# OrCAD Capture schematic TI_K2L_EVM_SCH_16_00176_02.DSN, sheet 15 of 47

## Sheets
15 PAGE38 : K2L_XDS200_2: size C; title: XDS200 / AM1802,  boot mode, reset, XDS200 power
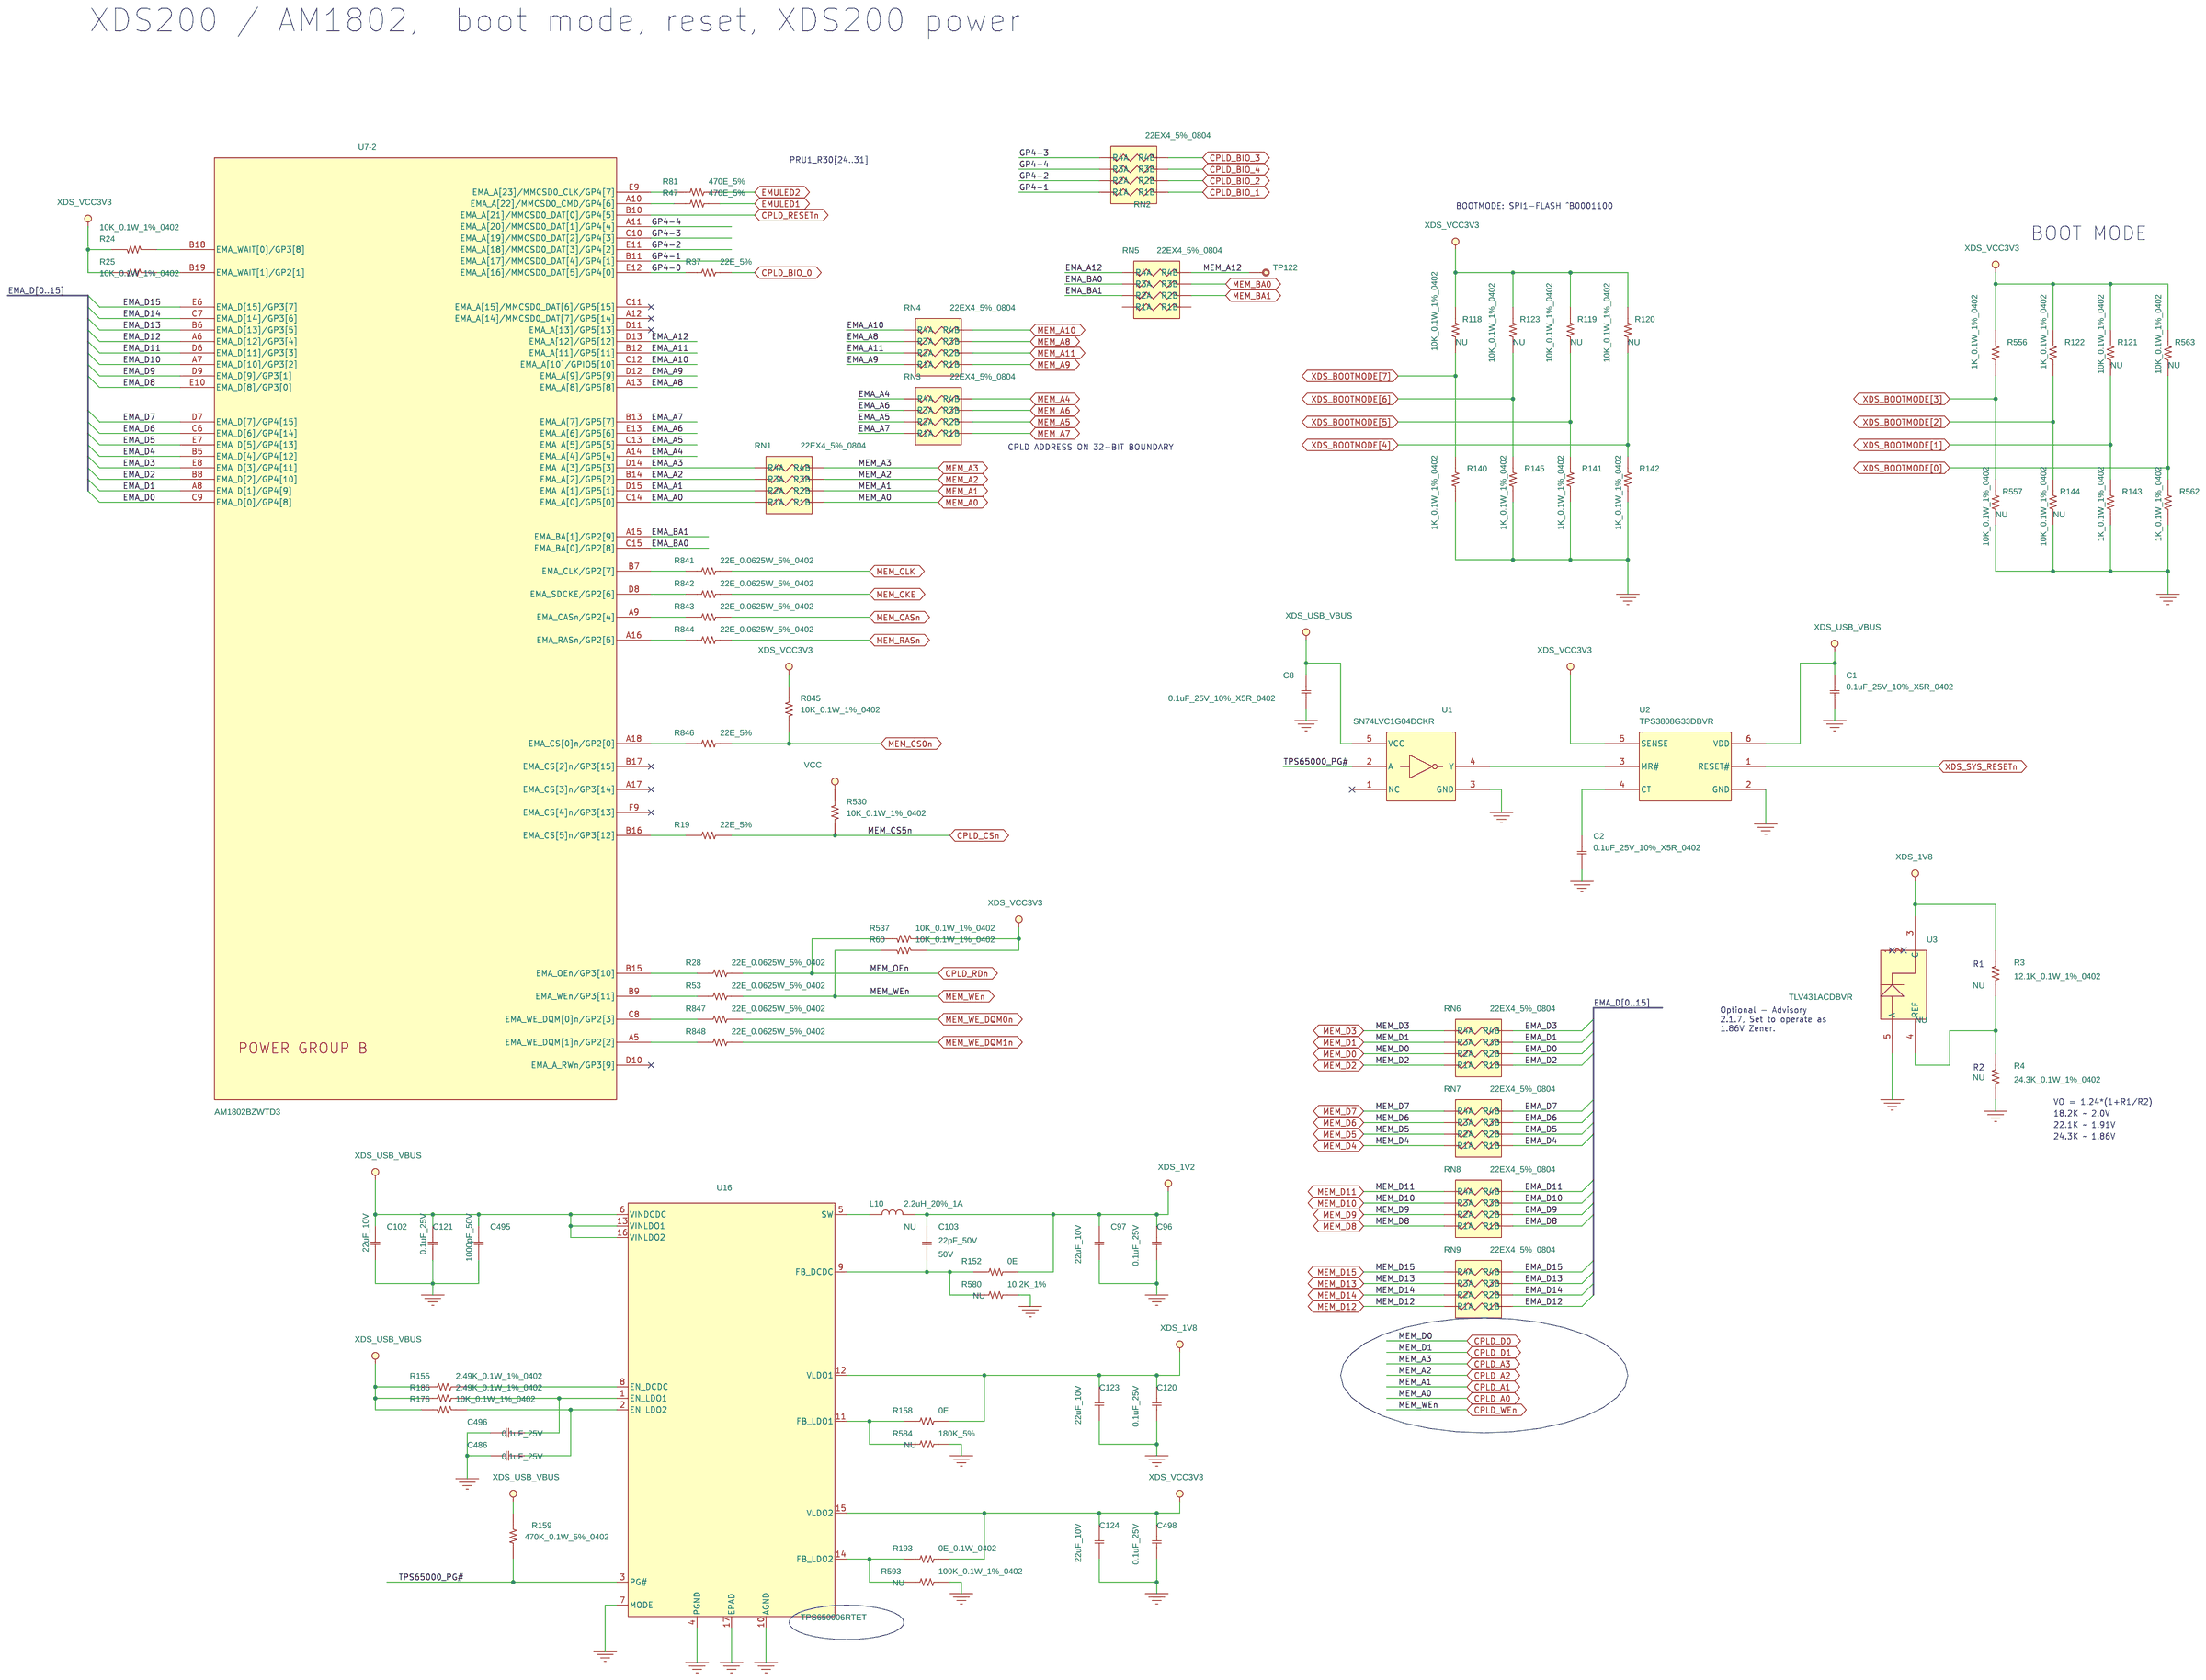
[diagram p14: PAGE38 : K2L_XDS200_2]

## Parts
sheet PAGE38 : K2L_XDS200_2
C1  0.1uF_25V_10%_X5R_0402  [C0402]
C2  0.1uF_25V_10%_X5R_0402  [C0402]
C8  0.1uF_25V_10%_X5R_0402  [C0402]
C96  0.1uF_25V  [C0402]
C97  22uF_10V  [C0805]
C102  22uF_10V  [C0805]
C103  22pF_50V  [C0402]
C120  0.1uF_25V  [C0402]
C121  0.1uF_25V  [C0402]
C123  22uF_10V  [C0805]
C124  22uF_10V  [C0805]
C486  0.1uF_25V  [C0402]
C495  1000pF_50V  [C0402]
C496  0.1uF_25V  [C0402]
C498  0.1uF_25V  [C0402]
L10  2.2uH_20%_1A  [IND1008]
R3  12.1K_0.1W_1%_0402  [R0402]
R4  24.3K_0.1W_1%_0402  [R0402]
R19  22E_5%  [R0402]
R24  10K_0.1W_1%_0402  [R0402]
R25  10K_0.1W_1%_0402  [R0402]
R28  22E_0.0625W_5%_0402  [R0402]
R37  22E_5%  [R0402]
R47  470E_5%  [R0402]
R53  22E_0.0625W_5%_0402  [R0402]
R60  10K_0.1W_1%_0402  [R0402]
R81  470E_5%  [R0402]
R118  10K_0.1W_1%_0402  [R0402]
R119  10K_0.1W_1%_0402  [R0402]
R120  10K_0.1W_1%_0402  [R0402]
R121  10K_0.1W_1%_0402  [R0402]
R122  1K_0.1W_1%_0402  [R0402]
R123  10K_0.1W_1%_0402  [R0402]
R140  1K_0.1W_1%_0402  [R0402]
R141  1K_0.1W_1%_0402  [R0402]
R142  1K_0.1W_1%_0402  [R0402]
R143  1K_0.1W_1%_0402  [R0402]
R144  10K_0.1W_1%_0402  [R0402]
R145  1K_0.1W_1%_0402  [R0402]
R152  0E  [R0402]
R155  2.49K_0.1W_1%_0402  [R0402]
R158  0E  [R0402]
R159  470K_0.1W_5%_0402  [R0402]
R176  10K_0.1W_1%_0402  [R0402]
R186  2.49K_0.1W_1%_0402  [R0402]
R193  0E_0.1W_0402  [R0402]
R530  10K_0.1W_1%_0402  [R0402]
R537  10K_0.1W_1%_0402  [R0402]
R556  1K_0.1W_1%_0402  [R0402]
R557  10K_0.1W_1%_0402  [R0402]
R562  1K_0.1W_1%_0402  [R0402]
R563  10K_0.1W_1%_0402  [R0402]
R580  10.2K_1%  [R0402]
R584  180K_5%  [R0402]
R593  100K_0.1W_1%_0402  [R0402]
R841  22E_0.0625W_5%_0402  [R0402]
R842  22E_0.0625W_5%_0402  [R0402]
R843  22E_0.0625W_5%_0402  [R0402]
R844  22E_0.0625W_5%_0402  [R0402]
R845  10K_0.1W_1%_0402  [R0402]
R846  22E_5%  [R0402]
R847  22E_0.0625W_5%_0402  [R0402]
R848  22E_0.0625W_5%_0402  [R0402]
RN1  22EX4_5%_0804  [RESN_EXBN8V_0402X4]
RN2  22EX4_5%_0804  [RESN_EXBN8V_0402X4]
RN3  22EX4_5%_0804  [RESN_EXBN8V_0402X4]
RN4  22EX4_5%_0804  [RESN_EXBN8V_0402X4]
RN5  22EX4_5%_0804  [RESN_EXBN8V_0402X4]
RN6  22EX4_5%_0804  [RESN_EXBN8V_0402X4]
RN7  22EX4_5%_0804  [RESN_EXBN8V_0402X4]
RN8  22EX4_5%_0804  [RESN_EXBN8V_0402X4]
RN9  22EX4_5%_0804  [RESN_EXBN8V_0402X4]
TP122  TP  [TP-S40]
U1  SN74LVC1G04DCKR  [SC70_5p]
U2  TPS3808G33DBVR  [SOT23_6]
U3  TLV431ACDBVR  [dbv-20x60-5]
U16  TPS650006RTET  [QFN50P300X300X80-17N_A_EINF]
sheet PAGE39 : K2L_XDS200_3
U7  AM1802BZWTD3  [BGA80P_16X16_361]  (sections -1,-10,-11,-12,-13,-14,-15,-16,-2,-3,-4,-5,-6,-7,-8,-9)

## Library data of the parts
C1 C2 C8 = 11_C_12: CAP CER 0.1UF 25V 10% X5R 0402; Alt Mfg: Taiyo Yuden; Distributor_name: DIGIKEY; Distributor_part_number: 445-4964-1-ND; EIC Part#: 03_00470_02; Manufacture: TDK Corporation; Manufacture Part Number: C1005X5R1E104K050BC; Manufacture(English): TDK Corporation; Manufacture_Part_Number: GRM155R61E104KA87D; Manufacturer: TDK Corporation; Manufacturer_Part_No: C1005X5R1E104K050BC; Mfg: Murata Electronics North America; Mfg Part#: 03_00470_02; Mfr_name: TDK Corporation; Mfr_part_number: C1005X5R1E104K050BC; Oper. Temp. Range: -55°C ~ 85°C; Package: 0402; Price @ 1: 0.10000; Price @ 1K: 0.00960; ProcessType: SMT; RoHS: Yes; Tolerance: 10%; Vendor: DIGIKEY; Vendor Part#: 445-4964-1-ND; Vendor_Part_No: 445-4964-1-ND; eI Part#: 03_00470_02
C96 C120 C121 C486 C496 C498 = 11_C_0: CAP CER 0.1UF 25V 10% X5R 0402; Alt Mfg: Taiyo Yuden; Distributor_name: DIGIKEY; Distributor_part_number: 445-4964-1-ND; EIC Part#: 03_00470_02; Manufacture: TDK Corporation; Manufacture Part Number: C1005X5R1E104K050BC; Manufacture(English): TDK Corporation; Manufacture_Part_Number: GRM155R61E104KA87D; Manufacturer: TDK Corporation; Manufacturer_Part_No: C1005X5R1E104K050BC; Mfg: Murata Electronics North America; Mfg Part#: 03_00470_02; Mfr_name: TDK Corporation; Mfr_part_number: C1005X5R1E104K050BC; Oper. Temp. Range: -55°C ~ 85°C; Package: 0402; Price @ 1: 0.10000; Price @ 1K: 0.00960; ProcessType: SMT; RoHS: Yes; Tolerance: 10%; Vendor: DIGIKEY; Vendor Part#: 445-4964-1-ND; Vendor_Part_No: 445-4964-1-ND; eI Part#: 03_00470_02
C97 C102 C123 C124 = 11_C_12: CAP CER 22UF 10V 20% X5R 0805; Characteristic: <Characteristic>; Distributor_name: DIGIKEY; Distributor_part_number: 587-1958-1-ND; EIC Part#: 03_00263_01; Manufacture: Taiyo Yuden; Manufacture Part Number: LMK212BJ226MG-T; Manufacture(English): Taiyo Yuden; Manufacture_Part_Number: LMK212BJ226MG-T; Manufacturer: Taiyo Yuden; Manufacturer_Part_No: LMK212BJ226MG-T; Mfg: Taiyo Yuden; Mfg Part#: 03_00263_01; Mfr_name: Taiyo Yuden; Mfr_part_number: LMK212BJ226MG-T; Oper. Temp. Range: -55C to 85C; Package: 0805; Price @ 1: 0.53000; Price @ 10K: 0.12000; Price @ 1K: 0.16875; ProcessType: SMT; RoHS: Yes; Tolerance: 20%; Vendor: DIGIKEY; Vendor Part#: 587-1958-1-ND; Vendor_Part_No: 587-1958-1-ND; Voltage: 10V; eI Part#: 03_00263_01
C103 = 11_C_0: CAP CER 22PF 50V 0402 SMD; Alt Mfg: Yageo; Alt Mfg Part#: CC0402JRNPO9BN220; Alternate_Mfr: TDK Corporation; Alternate_Partno: C1005C0G1H220J050BA; Distributor_name: DIGIKEY; Distributor_part_number: PCC220CQCT-ND; EIC Part#: 03_00204_02; Manufacture: Panasonic - ECG; Manufacture Part Number: ECJ-0EC1H220J; Manufacture(English): Panasonic - ECG; Manufacture_Part_Number: ECJ-0EC1H220J; Manufacturer: Panasonic - ECG; Manufacturer_Part_No: ECJ-0EC1H220J; Mfg: Panasonic - ECG; Mfg Part#: 03_00204_02; Mfr_name: Panasonic - ECG; Mfr_part_number: ECJ-0EC1H220J; Mounting Status: NU; Mounting_Status: NU; Oper. Temp. Range: -55C to 125C; Package: 0402; Price @ 1: TBD; Price @ 10K: TBD; Price @ 1K: TBD; ProcessType: SMT; RoHS: Yes; Tolerance: 5%; Vendor: DIGIKEY; Vendor Part#: PCC220CQCT-ND; Vendor_Part_No: PCC220CQCT-ND; Voltage: 50V; eI Part#: 03_00204_02
C495 = 11_C_0: CAP CER 1000PF 50V 10% X7R 0402; Advansus_Part_Number: 11G232110214030; Distributor_name: DIGIKEY; Distributor_part_number: 1276-1493-1-ND; EIC Part#: 03_00591_01; Manufacture: Samsung; Manufacture Part Number: CL05B102KB5NFNC; Manufacture(English): Samsung; Manufacture_Part_Number: CL05B102KB5NFNC; Manufacturer: Samsung; Manufacturer_Part_No: CL05B102KB5NFNC; Mfg: Samsung; Mfg Part#: CL05B102KB5NFNC; Mfr_name: Samsung; Mfr_part_number: CL05B102KB5NFNC; Oper. Temp. Range: -55C to 85C; Package: 0402; Price @ 1: 0.10000; Price @ 10K: 0.00260; Price @ 1K: 0.00372; ProcessType: SMT; RoHS: Yes; Tolerance: 10%; Vendor: DIGIKEY; Vendor Part#: 1276-1493-1-ND; Vendor_Part_No: 1276-1493-1-ND; Voltage: 50V; eI Part#: 03_00591_01
L10 = 1211_CHOKE_0: INDUCTOR 2.2UH; Current: 2.3A Irms; Distributor_name: DIGIKEY; Distributor_part_number: 490-6700-1-ND; EIC Part#: 04_00407_01; Manufacture: Murata; Manufacture Part Number: LQM2HPN2R2MJ0L; Manufacture(English): Murata; Manufacture_Part_Number: LQM2HPN2R2MJ0L; Manufacturer: Murata; Manufacturer_Part_No: LQM2HPN2R2MJ0L; Mfg Part#: 04_00407_01; Mfr_name: Murata; Mfr_part_number: LQM2HPN2R2MJ0L; ProcessType: SMT; RoHS: Yes; Tolerance: 20%; Vendor: DIGIKEY; Vendor Part#: LQM2HPN2R2MJ0L; Vendor_Part_No: 490-6700-1-ND; eI Part#: 04_00407_01
R3 = 10_R_0: RES 12.1K OHM 1/10W 1% 0402 SMD; Alt Mfg: Yageo; Alt Mfg Part#: RC0402FR-0710KL; Distributor_name: DIGIKEY; Distributor_part_number: P12.1KLCT-ND; EIC Part#: 02_00497_01; Manufacture: Panasonic - ECG; Manufacture Part Number: ERJ-2RKF1212X; Manufacture(English): Panasonic - ECG; Manufacture_Part_Number: ERJ-2RKF1212X; Manufacturer: Panasonic - ECG; Manufacturer_Part_No: ERJ-2RKF1212X; Mfg Part#: 02_00497_01; Mfr_name: Panasonic - ECG; Mfr_part_number: ERJ-2RKF1212X; Mounting: NU; Mounting Status: NU; Mounting_Status: NU; Oper. Temp. Range: -55C to 125C; Package: 0402; ProcessType: SMT; Remark: Alt part is 1/16W; RoHS: Yes; Tolerance: 1%; Vendor: DIGIKEY; Vendor Part#: P12.1KLDKR-ND; Vendor_Part_No: P12.1KLCT-ND; eI Part#: 02_00027_01
R4 = 10_R_0: RES 24.3K OHM 1/10W 1% 0402 SMD; Alt Mfg: Yageo; Alt Mfg Part#: RC0402FR-0710KL; Distributor_name: DIGIKEY; Distributor_part_number: P24.3KLCT-ND; EIC Part#: 02_00786_01; Manufacture: Panasonic - ECG; Manufacture Part Number: ERJ-2RKF2432X; Manufacture(English): Panasonic - ECG; Manufacture_Part_Number: ERJ-2RKF2432X; Manufacturer: Panasonic - ECG; Manufacturer_Part_No: ERJ-2RKF2432X; Mfg Part#: 02_00786_01; Mfr_name: Panasonic - ECG; Mfr_part_number: ERJ-2RKF2432X; Mounting: NU; Mounting Status: NU; Mounting_Status: NU; Oper. Temp. Range: -55C to 125C; Package: 0402; ProcessType: SMT; Remark: Alt part is 1/16W; RoHS: Yes; Tolerance: 1%; Vendor: DIGIKEY; Vendor Part#: P24.3KLCT-ND; Vendor_Part_No: P24.3KLCT-ND; eI Part#: 02_00497_01
R19 R28 R37 R53 R841-R844 R846-R848 = 10_R_0: RES 22 OHM 1/16W 1% 0402 SMD; Characteristic: 5%; Distributor_name: DIGIKEY; Distributor_part_number: P22JCT-ND; EIC Part#: 02_00233_01; Manufacture: Panasonic - ECG; Manufacture Part Number: ERJ-2GEJ220X; Manufacture(English): Panasonic - ECG; Manufacture_Part_Number: ERJ-2GEJ220X; Manufacturer: Panasonic - ECG; Manufacturer_Part_No: ERJ-2GEJ220X; Mfg: Panasonic - ECG; Mfg Part#: ERJ-2GEJ220X; Mfr_name: Panasonic - ECG; Mfr_part_number: ERJ-2GEJ220X; Oper. Temp. Range: -55C to 125C; Package: 0402; ProcessType: SMT; RoHS: Yes; Tolerance: 5%; Vendor: DIGIKEY; Vendor Part#: P22JCT-ND; Vendor_Part_No: P22JCT-ND; eI Part#: 02_00233_01
R24 R25 R60 R530 R537 R845 = 10_R_0: RES 10K OHM 1/10W 1% 0402 SMD; Alt Mfg: Yageo; Alt Mfg Part#: RC0402FR-0710KL; Distributor_name: DIGIKEY; Distributor_part_number: P10.0KLCT-ND; EIC Part#: 02_00027_01; Manufacture: Panasonic - ECG; Manufacture Part Number: ERJ-2RKF1002X; Manufacture(English): Panasonic - ECG; Manufacture_Part_Number: ERJ-2RKF1002X; Manufacturer: Panasonic - ECG; Manufacturer_Part_No: ERJ-2RKF1002X; Mfg Part#: 02_00027_01; Mfr_name: Panasonic - ECG; Mfr_part_number: ERJ-2RKF1002X; Oper. Temp. Range: -55C ~ 125C; Package: 0402; Price @ 1: 0.10000; Price @ 10K: 0.00347; Price @ 1K: 0.00672; ProcessType: SMT; Remark: Alt part is 1/16W; RoHS: Yes; Tolerance: 1%; Vendor: DIGIKEY; Vendor Part#: P10.0KLCT-ND; Vendor_Part_No: P10.0KLCT-ND; eI Part#: 02_00027_01
R47 = 10_R_0: RES 470 OHM 1/10W 5% 0402 SMD; Alt Mfg: Yageo; Alt Mfg Part#: RC0402JR-070RL; Distributor_name: DIGIKEY; Distributor_part_number: P470JCT-ND; EIC Part#: 02_00483_01; Manufacture: Panasonic - ECG; Manufacture Part Number: ERJ-2GEJ471X; Manufacture(English): Panasonic - ECG; Manufacture_Part_Number: ERJ-2GEJ471X; Manufacturer: Panasonic - ECG; Manufacturer_Part_No: ERJ-2GEJ471X; Mfg Part#: 02_00483_01; Mfr_name: Panasonic - ECG; Mfr_part_number: ERJ-2GEJ471X; Oper. Temp. Range: -55C to 125C; Package: 0402; ProcessType: SMT; Remark: Alt part is 1/16W; RoHS: Yes; Tolerance: 5%; Vendor: DIGIKEY; Vendor Part#: P470JDKR-ND; Vendor_Part_No: P470JCT-ND; eI Part#: 02_00483_01
R81 = 10_R_0: RES 470 OHM 1/10W 5% 0402 SMD; Alt Mfg: Yageo; Alt Mfg Part#: RC0402JR-070RL; Distributor_name: DIGIKEY; Distributor_part_number: P470JCT-ND; EIC Part#: 02_00483_01; Manufacture: Panasonic - ECG; Manufacture Part Number: ERJ-2GEJ471X; Manufacture(English): Panasonic - ECG; Manufacture_Part_Number: ERJ-2GEJ471X; Manufacturer: Panasonic - ECG; Manufacturer_Part_No: ERJ-2GEJ471X; Mfg Part#: 02_00483_01; Mfr_name: Panasonic - ECG; Mfr_part_number: ERJ-2GEJ471X; Oper. Temp. Range: -55C to 125C; Package: 0402; ProcessType: SMT; Remark: Alt part is 1/16W; RoHS: Yes; Tolerance: 5%; Vendor: DIGIKEY; Vendor Part#: P470JDKR-ND; Vendor_Part_No: P470JCT-ND; eI Part#: 02_00027_01
R118-R120 R123 = 10_R_0: RES 10K OHM 1/10W 1% 0402 SMD; Alt Mfg: Yageo; Alt Mfg Part#: RC0402FR-0710KL; Distributor_name: DIGIKEY; Distributor_part_number: P10.0KLCT-ND; EIC Part#: 02_00027_01; Manufacture: Panasonic - ECG; Manufacture Part Number: ERJ-2RKF1002X; Manufacture(English): Panasonic - ECG; Manufacture_Part_Number: ERJ-2RKF1002X; Manufacturer: Panasonic - ECG; Manufacturer_Part_No: ERJ-2RKF1002X; Mfg Part#: 02_00027_01; Mfr_name: Panasonic - ECG; Mfr_part_number: ERJ-2RKF1002X; Mounting: NU; Mounting Status: NU; Mounting_Status: NU; Oper. Temp. Range: -55C ~ 125C; Package: 0402; Price @ 1: 0.10000; Price @ 10K: 0.00347; Price @ 1K: 0.00672; ProcessType: SMT; Remark: Alt part is 1/16W; RoHS: Yes; Tolerance: 1%; Vendor: DIGIKEY; Vendor Part#: P10.0KLCT-ND; Vendor_Part_No: P10.0KLCT-ND; eI Part#: 02_00027_01
R121 R144 R557 R563 = 10_R_0: RES 10K OHM 1/10W 1% 0402 SMD; Alt Mfg: Yageo; Alt Mfg Part#: RC0402FR-0710KL; Distributor_name: DIGIKEY; Distributor_part_number: P10.0KLCT-ND; EIC Part#: 02_00027_01; Manufacture: Panasonic - ECG; Manufacture Part Number: ERJ-2RKF1002X; Manufacture(English): Panasonic - ECG; Manufacture_Part_Number: ERJ-2RKF1002X; Manufacturer: Panasonic - ECG; Manufacturer_Part_No: ERJ-2RKF1002X; Mfg Part#: 02_00027_01; Mfr_name: Panasonic - ECG; Mfr_part_number: ERJ-2RKF1002X; Mounting: NU; Mounting Status: NU; Mounting_Status: NU; Oper. Temp. Range: -55C ~ 125C; Package: 0402; Price @ 1: 0.10000; Price @ 10K: 0.00347; Price @ 1K: 0.00672; ProcessType: SMT; Remark: Alt part is 1/16W; RoHS: Yes; Vendor: DIGIKEY; Vendor Part#: P10.0KLCT-ND; Vendor_Part_No: P10.0KLCT-ND; eI Part#: 02_00027_01
R122 R143 R556 R562 = 10_R_0: RES 1.00K OHM 1/10W 1% 0402 SMD; Alt Mfg: Yageo; Distributor_name: DIGIKEY; Distributor_part_number: P1.00KLCT-ND; EIC Part#: 02_00045_01; MOUNTED: <MOUNTED>; Manufacture: Panasonic - ECG; Manufacture Part Number: ERJ-2RKF1001X; Manufacture(English): Panasonic - ECG; Manufacture_Part_Number: ERJ-2RKF1001X; Manufacturer: Panasonic - ECG; Manufacturer_Part_No: ERJ-2RKF1001X; Mfg Part#: 02_00045_01; Mfr_name: Panasonic - ECG; Mfr_part_number: ERJ-2RKF1001X; Oper. Temp. Range: -55C to 125C; Package: 0402; ProcessType: SMT; RoHS: Yes; Vendor: DIGIKEY; Vendor Part#: P1.00KLCT-ND; Vendor_Part_No: P1.00KLCT-ND; eI Part#: 02_00045_01
R140-R142 R145 = 10_R_0: RES 1.00K OHM 1/10W 1% 0402 SMD; Alt Mfg: Yageo; Distributor_name: DIGIKEY; Distributor_part_number: P1.00KLCT-ND; EIC Part#: 02_00045_01; MOUNTED: <MOUNTED>; Manufacture: Panasonic - ECG; Manufacture Part Number: ERJ-2RKF1001X; Manufacture(English): Panasonic - ECG; Manufacture_Part_Number: ERJ-2RKF1001X; Manufacturer: Panasonic - ECG; Manufacturer_Part_No: ERJ-2RKF1001X; Mfg Part#: 02_00045_01; Mfr_name: Panasonic - ECG; Mfr_part_number: ERJ-2RKF1001X; Oper. Temp. Range: -55C to 125C; Package: 0402; ProcessType: SMT; RoHS: Yes; Tolerance: 1%; Vendor: DIGIKEY; Vendor Part#: P1.00KLCT-ND; Vendor_Part_No: P1.00KLCT-ND; eI Part#: 02_00045_01
R152 R158 R193 = 10_R_0: RES 0.0 OHM 1/10W JUMP 0402 SMD; Alt Mfg: Yageo; Distributor_name: DIGIKEY; Distributor_part_number: P0.0JCT-ND; EIC Part#: 02_00019_01; Manufacture: Panasonic - ECG; Manufacture Part Number: ERJ-2GE0R00X; Manufacture(English): Panasonic - ECG; Manufacture_Part_Number: ERJ-2GE0R00X; Manufacturer: Panasonic - ECG; Manufacturer_Part_No: ERJ-2GE0R00X; Mfg Part#: 02_00019_01; Mfr_name: Panasonic - ECG; Mfr_part_number: ERJ-2GE0R00X; Oper. Temp. Range: -55C to 125C; Package: 0402; ProcessType: SMT; Remark: Alt part is 1/16W; RoHS: Yes; Tolerance: 5%; Vendor: DIGIKEY; Vendor Part#: P0.0JCT-ND; Vendor_Part_No: P0.0JCT-ND; eI Part#: 02_00019_01
R155 R186 = 10_R_0: RES 2.49K OHM 1/10W 1% 0402 SMD; Alt Mfg: Yageo; Alt Mfg Part#: RC0402FR-071KL; Distributor_name: DIGIKEY; Distributor_part_number: P2.49KLCT-ND; EIC Part#: 02_00794_01; MOUNTED: <MOUNTED>; Manufacture: Panasonic - ECG; Manufacture Part Number: ERJ-2RKF2491X; Manufacture(English): Panasonic - ECG; Manufacture_Part_Number: ERJ-2RKF2491X; Manufacturer: Panasonic - ECG; Manufacturer_Part_No: ERJ-2RKF2491X; Mfg Part#: 02_00794_01; Mfr_name: Panasonic - ECG; Mfr_part_number: ERJ-2RKF2491X; Oper. Temp. Range: -55C to 125C; Package: 0402; ProcessType: SMT; RoHS: Yes; Vendor: DIGIKEY; Vendor Part#: P2.49KLTR-ND; Vendor_Part_No: P2.49KLCT-ND; eI Part#: NA
R159 = 10_R_0: RES 470K OHM 1/10W 5% 0402 SMD; Alt Mfg: Yageo; Alt Mfg Part#: RC0402FR-0710KL; Distributor_name: DIGIKEY; Distributor_part_number: P470KJCT-ND; EIC Part#: 02_00200_04; Manufacture: Panasonic - ECG; Manufacture Part Number: ERJ-2GEJ474X; Manufacture(English): Panasonic - ECG; Manufacture_Part_Number: ERJ-2GEJ474X; Manufacturer: Panasonic - ECG; Manufacturer_Part_No: ERJ-2GEJ474X; Mfg Part#: 02_00200_04; Mfr_name: Panasonic - ECG; Mfr_part_number: ERJ-2GEJ474X; Oper. Temp. Range: -55C ~ 125C; Package: 0402; ProcessType: SMT; Remark: Alt part is 1/10W; RoHS: Yes; Tolerance: 1%; Vendor: DIGIKEY; Vendor Part#: P470KJCT-ND; Vendor_Part_No: P470KJCT-ND; eI Part#: NA
R176 = 10_R_0: RES 10K OHM 1/10W 1% 0402 SMD; Alt Mfg: Yageo; Alt Mfg Part#: RC0402FR-0710KL; Distributor_name: DIGIKEY; Distributor_part_number: P10.0KLCT-ND; EIC Part#: 02_00027_01; Manufacture: Panasonic - ECG; Manufacture Part Number: ERJ-2RKF1002X; Manufacture(English): Panasonic - ECG; Manufacture_Part_Number: ERJ-2RKF1002X; Manufacturer: Panasonic - ECG; Manufacturer_Part_No: ERJ-2RKF1002X; Mfg Part#: 02_00027_01; Mfr_name: Panasonic - ECG; Mfr_part_number: ERJ-2RKF1002X; Oper. Temp. Range: -55C ~ 125C; Package: 0402; Price @ 1: 0.10000; Price @ 10K: 0.00347; Price @ 1K: 0.00672; ProcessType: SMT; Remark: Alt part is 1/16W; RoHS: Yes; Vendor: DIGIKEY; Vendor Part#: P10.0KLCT-ND; Vendor_Part_No: P10.0KLCT-ND; eI Part#: 02_00027_01
R580 = 10_R_0: RES 10.2K OHM 1/10W 1% 0402 SMD; Alt Mfg: Yageo; Alt Mfg Part#: RC0402FR-0710KL; Distributor_name: ELEMENT14; Distributor_part_number: 2282634; EIC Part#: 02_00720_01; Manufacture: Panasonic - ECG; Manufacture Part Number: ERJ-2RKF1022X; Manufacture(English): Panasonic - ECG; Manufacture_Part_Number: ERJ-2RKF1022X; Manufacturer: Panasonic - ECG; Manufacturer_Part_No: ERJ-2RKF1022X; Mfg Part#: 02_00720_01; Mfr_name: Panasonic - ECG; Mfr_part_number: ERJ-2RKF1022X; Mounting Status: NU; Mounting_Status: NU; Oper. Temp. Range: -55C ~ 125C; Package: 0402; ProcessType: SMT; Remark: Alt part is 1/10W; RoHS: Yes; Tolerance: 1%; Vendor: ELEMENT14; Vendor Part#: P10.2KLCT-ND; Vendor_Part_No: 2282634; eI Part#: 02_00027_01
R584 = 10_R_0: RES 180K OHM 1/10W 5% 0402 SMD; Alt Mfg: Yageo; Alt Mfg Part#: RC0402FR-0710KL; Distributor_name: DIGIKEY; Distributor_part_number: P180KJCT-ND; EIC Part#: TBD; Manufacture: Panasonic - ECG; Manufacture Part Number: ERJ-2GEJ184X; Manufacture(English): Panasonic - ECG; Manufacture_Part_Number: ERJ-2GEJ184X; Manufacturer: Panasonic - ECG; Manufacturer_Part_No: ERJ-2GEJ184X; Mfg Part#: TBD; Mfr_name: Panasonic - ECG; Mfr_part_number: ERJ-2GEJ184X; Mounting Status: NU; Mounting_Status: NU; Oper. Temp. Range: -55C ~ 125C; Package: 0402; ProcessType: SMT; Remark: Alt part is 1/10W; RoHS: Yes; Tolerance: 1%; Vendor: DIGIKEY; Vendor Part#: P180KJCT-ND; Vendor_Part_No: P180KJCT-ND; eI Part#: NA
R593 = 10_R_0: RES 100K OHM 1/10W 1% 0402 SMD; Alt Mfg: Yageo; Alt Mfg Part#: RC0402FR-07100KL; Distributor_name: DIGIKEY; Distributor_part_number: P100KLCT-ND; EIC Part#: 02_00262_01; Manufacture: Panasonic - ECG; Manufacture Part Number: ERJ-2RKF1003X; Manufacture(English): Panasonic - ECG; Manufacture_Part_Number: ERJ-2RKF1003X; Manufacturer: Panasonic - ECG; Manufacturer_Part_No: ERJ-2RKF1003X; Mfg Part#: 02_00262_01; Mfr_name: Panasonic - ECG; Mfr_part_number: ERJ-2RKF1003X; Mounting Status: NU; Mounting_Status: NU; Oper. Temp. Range: ±100ppm/°C; Package: 0402; ProcessType: SMT; RoHS: Yes; Tolerance: 1%; Vendor: DIGIKEY; Vendor Part#: P100KLCT-ND; Vendor_Part_No: P100KLCT-ND; eI Part#: 02_00019_01
RN1-RN9 = R-Pak4: RES ARRAY 22 OHM 4 RES 0804; Distributor_name: DigiKey; Distributor_part_number: Y10220CT-ND; EIC Part#: 02_00972_01; Manufacture: Panasonic - ECG; Manufacture Part Number: EXB-N8V220JX; Manufacture(English): Panasonic - ECG; Manufacture_Part_Number: EXB-N8V220JX; Manufacturer: Panasonic - ECG; Manufacturer_Part_No: EXB-N8V220JX; Mfg: Panasonic - ECG; Mfg Part#: EXB-N8V220JX; Mfr_name: Panasonic - ECG; Mfr_part_number: EXB-N8V220JX; Oper. Temp. Range: -55°C ~ 125°C; Package: 0804; RoHS: Yes; Tolerance: 5%; Vendor: DigiKey; Vendor Part#: Y10220CT-ND; Vendor_Part_No: Y10220CT-ND; eI Part#: 02_00972_01
TP122 = 00_TP-S40_0: TEST PAD TP; Distributor_name: NA; Distributor_part_number: NA; EIC Part#: NA; Manufacture: NA; Manufacture Part Number: NA; Manufacture(English): NA; Manufacture_Part_Number: NA; Manufacturer: NA; Manufacturer_Part_No: NA; Mfg: NA; Mfg Part#: NA; Mfr_name: NA; Mfr_part_number: NA; Oper. Temp. Range: --NA--; Package: --NA--; Price @ 1: NA; Price @ 10K: NA; Price @ 1K: NA; ProcessType: SMT; RoHS: Yes; Vendor: NA; Vendor Part#: --NA--; Vendor_Part_No: NA; eI Part#: NA
U1 = SN74LVC1G06DRLR_1: IC SINGLE INVERTER GATE SC70-5; Distributor_name: DIGIKEY; Distributor_part_number: 296-11600-1-ND; EIC Part#: 01_00039_01; Manufacture: TI; Manufacture(English): TI; Manufacturer: TI; Mfg: TI; Mfg Part#: 01_00039_01; Mfr_name: TI; Oper. Temp. Range: -40C to 85C; Package: SC-70-5; Price @ 1: 0.49000; Price @ 10K: 0.09000; Price @ 1K: 0.10300; RoHS: Yes; Specifications: IC INVERTER SINGLE 1INPUT SOT553; Vendor: DIGIKEY; Vendor Part#: 296-18009-1-ND; Vendor_Part_No: 296-11600-1-ND; eI Part#: 01_00039_01
U2 = TPS3808G: IC VOLT SUPERVISOR 3.3V SOT23-6; Distributor_name: DIGIKEY; Distributor_part_number: 296-17195-1-ND; EIC Part#: 01_00570_01; Manufacture: TI; Manufacture(English): TI; Manufacturer: TI; Mfg: TI; Mfg Part#: 01_00570_01; Mfr_name: TI; Price @ 1: 1.95000; Price @ 10K: 0.76500; Price @ 1K: 0.78031; Specifications: IC VOLT SUPERVISOR 3.3V SOT23-6; Vendor: DIGIKEY; Vendor Part#: 296-17195-1-ND; Vendor_Part_No: 296-17195-1-ND; eI Part#: TBD
U3 = TLV431ACDBVR: IC VREF SHUNT PREC ADJ SOT-23-5; Distributor_name: DIGIKEY; Distributor_part_number: 296-1348-1-ND; EIC Part#: 01_00404_01; Manufacture: TI; Manufacture(English): TI; Manufacturer: TI; Mfg: TI; Mfg Part#: 01_00404_01; Mfr_name: TI; Mounting: NU; Mounting Status: NU; Mounting_Status: NU; Package: SOT-23-5; Part #: 101647-0001R; Price @ 1: 0.74000; Price @ 10K: 0.24300; Price @ 1K: 0.29700; RoHS: Yes; Vendor: DIGIKEY; Vendor Part#: 296-1348-1-ND; Vendor_Part_No: 296-1348-1-ND; eI Part#: TBD
U16 = TPS65000_6: IC CONV STP-DWN 2.25MHZ DL 16QFN; Distributor_name: DIGIKEY; Distributor_part_number: 296-25357-1-ND; EIC Part#: TBD; Manufacture: TI; Manufacture(English): TI; Manufacturer: TI; Mfg: TI; Mfr_name: TI; Price @ 1: 4.28000; Price @ 1K: 1.96764; Vendor: DIGIKEY; Vendor_Part_No: 296-25357-1-ND; eI Part#: TBD
U7 = OMAP-L138_new_5: IC ARM9 CORTEX MPU 361NFBGA; Distributor_name: DIGIKEY; Distributor_part_number: AM1802BZWTD3-ND; EIC Part#: 01_01135_01; Manufacture: TI; Manufacture(English): TI; Manufacturer: TI; Mfg: TI; Mfg Part#: 01_01135_01; Mfr_name: TI; Part #: 103922-0001R; Price @ 1: 14.51000; Price @ 1K: 14.51000; Vendor: DIGIKEY; Vendor_Part_No: AM1802BZWTD3-ND; eI Part#: 01_01147_01

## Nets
GND: C1.2 C2.2 C8.2 C96.2 C97.2 C102.2 C120.2 C121.2 C123.2 C124.2 C486.1 C495.1 C496.1 C498.2 R4.2 R140.1 R141.1 R142.1 R143.1 R144.2 R145.1 R557.2 R562.1 R580.1 R584.2 R593.1 U1.3(GND) U2.2(GND) U3.5(A) U16.4(PGND) U16.7(MODE) U16.10(AGND) U16.17(EPAD) ; also on sheet 1 2 3 4 5 6 8 10 11 12 13 14 16 17 18 19 20 21 22 24 25 26 27 28 29 33 34 35 36 37 40 41 42 43 45 46 47
CPLD_A0: RN1.8(R1B) ; also on sheet 42
CPLD_A1: RN1.7(R2B) ; also on sheet 42
CPLD_A2: RN1.6(R3B) ; also on sheet 42
CPLD_A3: RN1.5(R4B) ; also on sheet 42
CPLD_BIO_0: R37.1 ; also on sheet 42
CPLD_BIO_1: RN2.8(R1B) ; also on sheet 42
CPLD_BIO_2: RN2.7(R2B) ; also on sheet 42
CPLD_BIO_3: RN2.5(R4B) ; also on sheet 42
CPLD_BIO_4: RN2.6(R3B) ; also on sheet 42
CPLD_CSn: R19.1 R530.1 ; also on sheet 42
CPLD_D0: RN6.2(R2A) ; also on sheet 42
CPLD_D1: RN6.3(R3A) ; also on sheet 42
CPLD_RDn: R28.1 R537.2 ; also on sheet 42
CPLD_RESETn: U7.B10(EMA_A[21]/MMCSD0_DAT[0]/GP4[5]) ; also on sheet 42
CPLD_WEn: R53.1 R60.2 ; also on sheet 42
EMA_A0: RN1.1(R1A) U7.C14(EMA_A[0]/GP5[0])
EMA_A1: RN1.2(R2A) U7.D15(EMA_A[1]/GP5[1])
EMA_A2: RN1.3(R3A) U7.B14(EMA_A[2]/GP5[2])
EMA_A3: RN1.4(R4A) U7.D14(EMA_A[3]/GP5[3])
EMA_A4: RN3.4(R4A) U7.A14(EMA_A[4]/GP5[4])
EMA_A5: RN3.2(R2A) U7.C13(EMA_A[5]/GP5[5])
EMA_A6: RN3.3(R3A) U7.E13(EMA_A[6]/GP5[6])
EMA_A7: RN3.1(R1A) U7.B13(EMA_A[7]/GP5[7])
EMA_A8: RN4.3(R3A) U7.A13(EMA_A[8]/GP5[8])
EMA_A9: RN4.1(R1A) U7.D12(EMA_A[9]/GP5[9])
EMA_A10: RN4.4(R4A) U7.C12(EMA_A[10]/GPIO5[10])
EMA_A11: RN4.2(R2A) U7.B12(EMA_A[11]/GP5[11])
EMA_A12: RN5.4(R4A) U7.D13(EMA_A[12]/GP5[12])
EMA_BA0: RN5.3(R3A) U7.C15(EMA_BA[0]/GP2[8])
EMA_BA1: RN5.2(R2A) U7.A15(EMA_BA[1]/GP2[9])
EMA_D0: RN6.7(R2B) U7.C9(EMA_D[0]/GP4[8])
EMA_D1: RN6.6(R3B) U7.A8(EMA_D[1]/GP4[9])
EMA_D2: RN6.8(R1B) U7.B8(EMA_D[2]/GP4[10])
EMA_D3: RN6.5(R4B) U7.E8(EMA_D[3]/GP4[11])
EMA_D4: RN7.8(R1B) U7.B5(EMA_D[4]/GP4[12])
EMA_D5: RN7.7(R2B) U7.E7(EMA_D[5]/GP4[13])
EMA_D6: RN7.6(R3B) U7.C6(EMA_D[6]/GP4[14])
EMA_D7: RN7.5(R4B) U7.D7(EMA_D[7]/GP4[15])
EMA_D8: RN8.8(R1B) U7.E10(EMA_D[8]/GP3[0])
EMA_D9: RN8.7(R2B) U7.D9(EMA_D[9]/GP3[1])
EMA_D10: RN8.6(R3B) U7.A7(EMA_D[10]/GP3[2])
EMA_D11: RN8.5(R4B) U7.D6(EMA_D[11]/GP3[3])
EMA_D12: RN9.8(R1B) U7.A6(EMA_D[12]/GP3[4])
EMA_D13: RN9.6(R3B) U7.B6(EMA_D[13]/GP3[5])
EMA_D14: RN9.7(R2B) U7.C7(EMA_D[14]/GP3[6])
EMA_D15: RN9.5(R4B) U7.E6(EMA_D[15]/GP3[7])
EMULED1: R47.2 ; also on sheet 10
EMULED2: R81.2 ; also on sheet 10
GP4-0: R37.2 U7.E12(EMA_A[16]/MMCSD0_DAT[5]/GP4[0])
GP4-1: RN2.1(R1A) U7.B11(EMA_A[17]/MMCSD0_DAT[4]/GP4[1])
GP4-2: RN2.2(R2A) U7.E11(EMA_A[18]/MMCSD0_DAT[3]/GP4[2])
GP4-3: RN2.4(R4A) U7.C10(EMA_A[19]/MMCSD0_DAT[2]/GP4[3])
GP4-4: RN2.3(R3A) U7.A11(EMA_A[20]/MMCSD0_DAT[1]/GP4[4])
MEM_A4: RN3.5(R4B) ; also on sheet 42
MEM_A5: RN3.7(R2B) ; also on sheet 42
MEM_A6: RN3.6(R3B) ; also on sheet 42
MEM_A7: RN3.8(R1B) ; also on sheet 42
MEM_A8: RN4.6(R3B) ; also on sheet 42
MEM_A9: RN4.8(R1B) ; also on sheet 42
MEM_A10: RN4.5(R4B) ; also on sheet 42
MEM_A11: RN4.7(R2B) ; also on sheet 42
MEM_A12: RN5.5(R4B) TP122.1
MEM_BA0: RN5.6(R3B) ; also on sheet 42
MEM_BA1: RN5.7(R2B) ; also on sheet 42
MEM_CASn: R843.1 ; also on sheet 42
MEM_CKE: R842.1 ; also on sheet 42
MEM_CLK: R841.1 ; also on sheet 42
MEM_CS0n: R845.1 R846.1 ; also on sheet 42
MEM_D2: RN6.1(R1A) ; also on sheet 42
MEM_D3: RN6.4(R4A) ; also on sheet 42
MEM_D4: RN7.1(R1A) ; also on sheet 42
MEM_D5: RN7.2(R2A) ; also on sheet 42
MEM_D6: RN7.3(R3A) ; also on sheet 42
MEM_D7: RN7.4(R4A) ; also on sheet 42
MEM_D8: RN8.1(R1A) ; also on sheet 42
MEM_D9: RN8.2(R2A) ; also on sheet 42
MEM_D10: RN8.3(R3A) ; also on sheet 42
MEM_D11: RN8.4(R4A) ; also on sheet 42
MEM_D12: RN9.1(R1A) ; also on sheet 42
MEM_D13: RN9.3(R3A) ; also on sheet 42
MEM_D14: RN9.2(R2A) ; also on sheet 42
MEM_D15: RN9.4(R4A) ; also on sheet 42
MEM_RASn: R844.1 ; also on sheet 42
MEM_WE_DQM0n: R847.1 ; also on sheet 42
MEM_WE_DQM1n: R848.1 ; also on sheet 42
TPS65000_PG#: R159.1 U1.2(A) U16.3(PG#)
XDS_1V2: C96.1 C97.1 C103.1 L10.2 R152.1 ; also on sheet 24
XDS_1V8: C120.1 C123.1 R3.1 R158.1 U3.3(C) U16.12(VLDO1) ; also on sheet 10 24 42
XDS_BOOTMODE[0]: R562.2 R563.2 ; also on sheet 14
XDS_BOOTMODE[1]: R121.2 R143.2 ; also on sheet 14
XDS_BOOTMODE[2]: R122.1 R144.1 ; also on sheet 14
XDS_BOOTMODE[3]: R556.1 R557.1 ; also on sheet 14
XDS_BOOTMODE[4]: R120.2 R142.2 ; also on sheet 14
XDS_BOOTMODE[5]: R119.2 R141.2 ; also on sheet 14
XDS_BOOTMODE[6]: R123.2 R145.2 ; also on sheet 14
XDS_BOOTMODE[7]: R118.2 R140.2 ; also on sheet 14
XDS_SYS_RESETn: U2.1(RESET#) ; also on sheet 14
XDS_USB_VBUS: C1.1 C8.1 C102.1 C121.1 C495.2 R155.2 R159.2 R176.2 R186.2 U1.5(VCC) U2.6(VDD) U16.6(VINDCDC) U16.13(VINLDO1) U16.16(VINLDO2) ; also on sheet 6 10
XDS_VCC3V3: C124.1 C498.1 R24.1 R25.1 R60.1 R118.1 R119.1 R120.1 R121.1 R122.2 R123.1 R193.1 R530.2 R537.1 R556.2 R563.1 R845.2 U2.5(SENSE) U16.15(VLDO2) ; also on sheet 10 14 24 42
N18199473: R28.2 U7.B15(EMA_OEn/GP3[10])
N18199475: R53.2 U7.B9(EMA_WEn/GP3[11])
N18199500: R81.1 U7.E9(EMA_A[23]/MMCSD0_CLK/GP4[7])
N18199502: R47.1 U7.A10(EMA_A[22]/MMCSD0_CMD/GP4[6])
N18199508: R19.2 U7.B16(EMA_CS[5]n/GP3[12])
N18199523: R24.2 U7.B18(EMA_WAIT[0]/GP3[8])
N18199525: R25.2 U7.B19(EMA_WAIT[1]/GP2[1])
N18200785: C2.1 U2.4(CT)
N18201370: C496.2 R186.1 U16.1(EN_LDO1)
N18201382: C486.2 R176.1 U16.2(EN_LDO2)
N18201493: L10.1 U16.5(SW)
N18201504: C103.2 R152.2 R580.2 U16.9(FB_DCDC)
N18201583: R158.2 R584.1 U16.11(FB_LDO1)
N18201660: R193.2 R593.2 U16.14(FB_LDO2)
N18201744: R155.1 U16.8(EN_DCDC)
N18268324: U1.4(Y) U2.3(MR#)
N19398338: R3.2 R4.1 U3.4(REF)
N22502660: R841.2 U7.B7(EMA_CLK/GP2[7])
N22502662: R842.2 U7.D8(EMA_SDCKE/GP2[6])
N22502664: R843.2 U7.A9(EMA_CASn/GP2[4])
N22502666: R844.2 U7.A16(EMA_RASn/GP2[5])
N22502724: R846.2 U7.A18(EMA_CS[0]n/GP2[0])
N22503434: R847.2 U7.C8(EMA_WE_DQM[0]n/GP2[3])
N22503445: R848.2 U7.A5(EMA_WE_DQM[1]n/GP2[2])

Not connected (* = marked no-connect by the designer): RN5 1(R1A) 8(R1B); U1 1(NC)*; U3 1* 2*; U7 A12(EMA_A[14]/MMCSD0_DAT[7]/GP5[14])* A17(EMA_CS[3]n/GP3[14])* B17(EMA_CS[2]n/GP3[15])* C11(EMA_A[15]/MMCSD0_DAT[6]/GP5[15])* D10(EMA_A_RWn/GP3[9])* D11(EMA_A[13]/GP5[13])* F9(EMA_CS[4]n/GP3[13])*

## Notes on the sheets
sheet 15
- XDS200 / AM1802,  boot mode, reset, XDS200 power
- PRU1_R30[24..31]
- BOOTMODE: SPI1-FLASH ^B0001100
- BOOT MODE
- CPLD ADDRESS ON 32-BIT BOUNDARY
- R1
- Optional - Advisory
  2.1.7, Set to operate as
  1.86V Zener.
- R2
- VO = 1.24*(1+R1/R2)
- 18.2K ~ 2.0V
- 22.1K ~ 1.91V
- 24.3K ~ 1.86V
